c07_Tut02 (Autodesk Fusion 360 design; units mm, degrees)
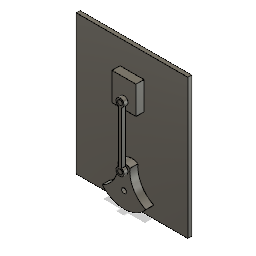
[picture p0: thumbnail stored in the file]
sketch "Sketch1"
  dimension "d1" = 30
  dimension "d2" = 35
  dimension "d3" = 6
  dimension "d4" = 5
  dimension "d5" = 10
  dimension "d6" = 15
  dimension "d8" = 4
  dimension "d9" = 5
  dimension "d10" = 75
  dimension "d11" = 15
  dimension "d13" = 35
  dimension "d14" = 70
  dimension "d15" = 70
  dimension "d16" = 60
  dimension "d18" = 6
  dimension "d21" = 23
  dimension "d99" = 140
  dimension "d100" = 175
  dimension "d101" = 55
  dimension "d102" = 30
  dimension "d127" = 8
extrude "Extrude1" new body sketch "Sketch1" blind -10
extrude "Extrude2" add sketch "Sketch1" blind 5
component_from_bodies "Body->Comp1"
extrude "Extrude1" new body sketch "Sketch1" blind 5 OffsetX 0 OffsetY 0 OffsetZ 0 AngleZ 0 OffsetX 0 OffsetY 0 OffsetZ 0 AngleZ 0
place_component sketch "Sketch1"
extrude "Extrude1" sketch "Sketch1" blind -10
extrude "Extrude3" sketch "Sketch1" blind 5
combine "Combine1"
component_from_bodies "Body->Comp2"
remove_instance "RemoveInstance1"
position "Position1"
joint "Assemble1" alignAngle 0 alignOffsetX 0 alignOffsetY 0 alignOffsetZ -2.5
position "Position2"
joint "Assemble3" alignAngle 0 alignOffsetX 0 alignOffsetY 0 alignOffsetZ -5
position "Position3"
joint "Assemble4" alignAngle 0 alignOffsetX 0 alignOffsetY 0 alignOffsetZ -5
position "Position4"
position "Position5"
extrude "Extrude1" new body sketch "Sketch1" blind -5 from offset -15
ground "Ground1"
position "Position7"
joint "Assemble6" alignAngle 0 alignOffsetX -55 alignOffsetY 0 alignOffsetZ -55
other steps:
base_feature "Base Feature1"
base_feature "Base Feature1" OffsetX 0 OffsetY 0 OffsetZ 0 AngleZ 0 OffsetX 0 OffsetY 0 OffsetZ 0 AngleZ 0
create_component "CreateComponent1"
remove_body "RemoveBody1"
create_component "CreateComponent2"
create_component "CreateComponent3" sketch "Sketch1"
remove_body "RemoveBody1" sketch "Sketch1"
create_component "CreateComponent4"
remove_body "RemoveBody2"
joint_origin "JointOrigin1" OffsetX 0 OffsetY 0 OffsetZ 0 AngleZ 0
joint_origin "JointOrigin4" OffsetX 0 OffsetY 0 OffsetZ 0 AngleZ 0
joint_origin "JointOrigin4" OffsetX 0 OffsetY 0 OffsetZ 0 AngleZ 0
joint_origin "JointOrigin5" OffsetX 0 OffsetY 0 OffsetZ 0 AngleZ 0
joint_origin "JointOrigin5" OffsetX 0 OffsetY 0 OffsetZ 0 AngleZ 0
joint_origin "JointOrigin1" OffsetX 0 OffsetY 0 OffsetZ 0 AngleZ 0
create_component "CreateComponent5"
joint_origin "JointOrigin3" OffsetX 0 OffsetY 0 OffsetZ 0 AngleZ 0
joint_origin "JointOrigin2" OffsetX 0 OffsetY 0 OffsetZ 0 AngleZ 0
